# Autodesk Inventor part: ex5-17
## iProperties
Shininess: 64.0
Length Units: 11272
Angle Units: 11279
Time Units: 11290
Mass Units: 11286
Length Display Precision: 3
Angle Display Precision: 2
Compacted: True
Part Number: ex5-17
Document SubType Name: Modeling
Created: 2003-11
Designer: Elise Moss
Cost Center: 0 lbmass
Authority: 0.89 in^3
Manufacturer: Standard
Standards Organization: Custom
Density: 0.0
Volumn: 0.0
Area: 0.0
PropertySet Name: Model Information
Control State: 0
Master: False
Checked Out: False
SaveDate: 2003-11-15
SaveTime: 19:59
TotalMass: 0 lbmass
TotalVolume: 0.89 in^3
Author: Elise Moss
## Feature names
1. Revolution1
2. Shell1
3. Extrusion2
4. Circular Pattern1
